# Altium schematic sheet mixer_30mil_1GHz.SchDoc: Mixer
size A4; Author: Almela; Revision: 1.2; SheetNumber: 2; SheetTotal: 7
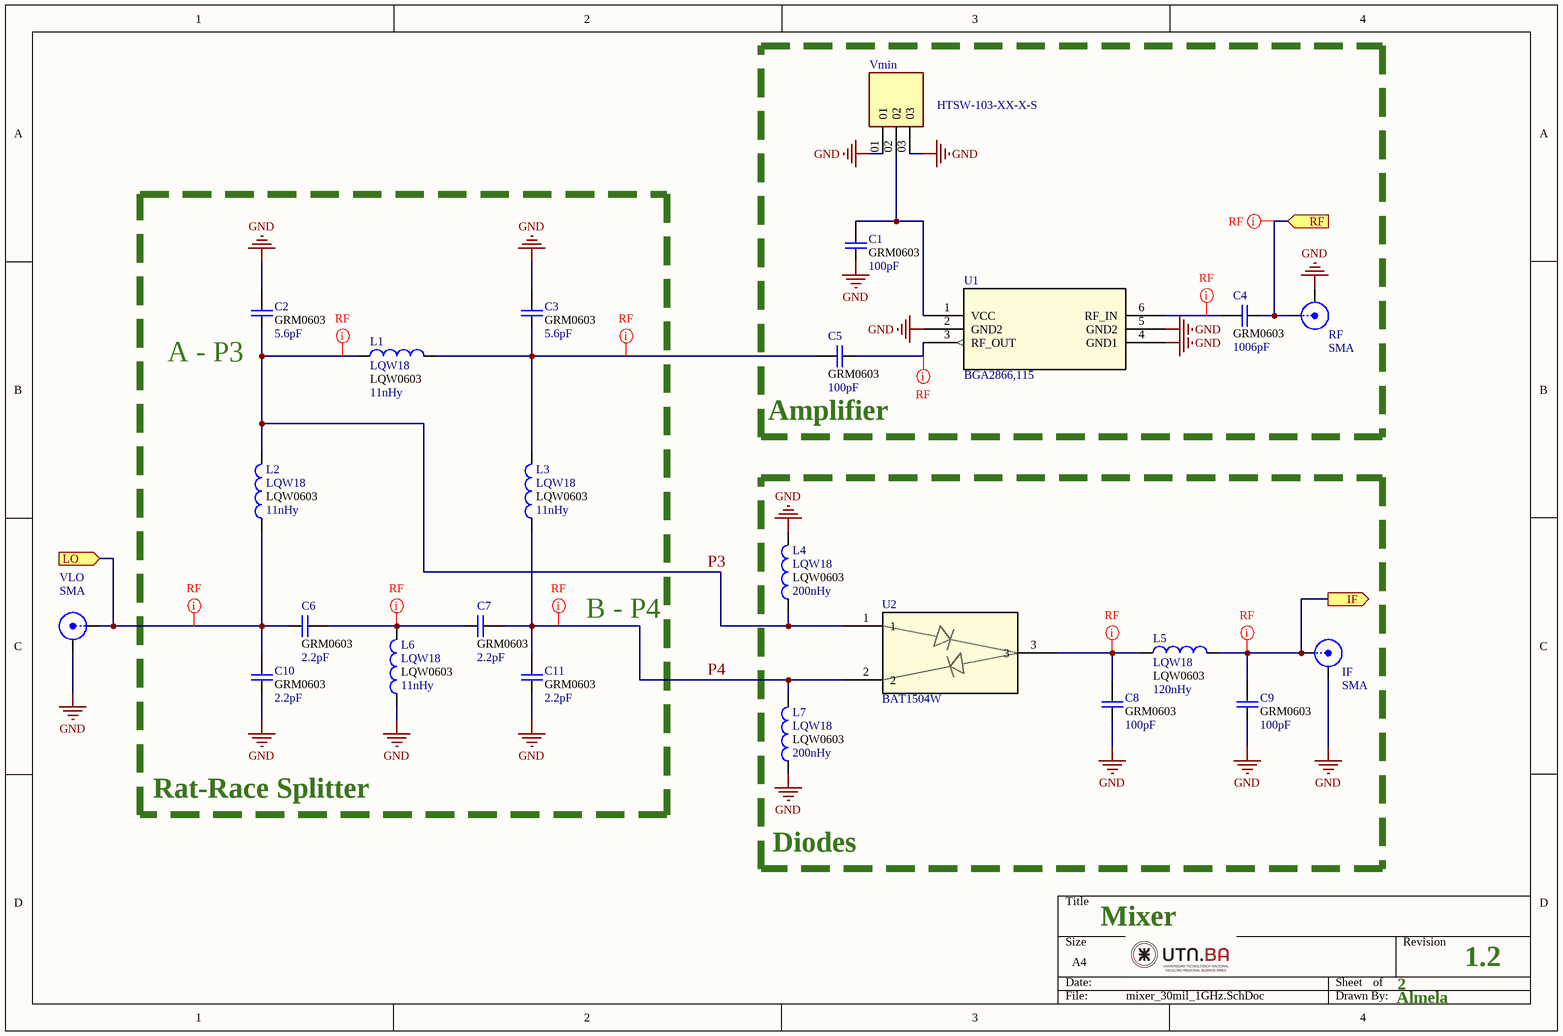
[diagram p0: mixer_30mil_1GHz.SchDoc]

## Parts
C1  value 100pF  footprint: GRM0603  [CAPC1608X90N]  (hidden comment: Cap 0603)
C2  value 5.6pF  footprint: GRM0603  [CAPC1608X90N]  (hidden comment: Cap 0603)
C3  value 5.6pF  footprint: GRM0603  [CAPC1608X90N]  (hidden comment: Cap 0603)
C4  value 1006pF  footprint: GRM0603  [CAPC1608X90N]  (hidden comment: Cap 0603)
C5  value 100pF  footprint: GRM0603  [CAPC1608X90N]  (hidden comment: Cap 0603)
C6  value 2.2pF  footprint: GRM0603  [CAPC1608X90N]  (hidden comment: Cap 0603)
C7  value 2.2pF  footprint: GRM0603  [CAPC1608X90N]  (hidden comment: Cap 0603)
C8  value 100pF  footprint: GRM0603  [CAPC1608X90N]  (hidden comment: Cap 0603)
C9  value 100pF  footprint: GRM0603  [CAPC1608X90N]  (hidden comment: Cap 0603)
C10  value 2.2pF  footprint: GRM0603  [CAPC1608X90N]  (hidden comment: Cap 0603)
C11  value 2.2pF  footprint: GRM0603  [CAPC1608X90N]  (hidden comment: Cap 0603)
IF  SMA  [SMA-142-0701-851]
L1  LQW18  value 11nHy  Parameter 1: LQW0603  [INDC1608X100N]
L2  LQW18  value 11nHy  Parameter 1: LQW0603  [INDC1608X100N]
L3  LQW18  value 11nHy  Parameter 1: LQW0603  [INDC1608X100N]
L4  LQW18  value 200nHy  Parameter 1: LQW0603  [INDC1608X100N]
L5  LQW18  value 120nHy  Parameter 1: LQW0603  [INDC1608X100N]
L6  LQW18  value 11nHy  Parameter 1: LQW0603  [INDC1608X100N]
L7  LQW18  value 200nHy  Parameter 1: LQW0603  [INDC1608X100N]
RF  SMA  [SMA-142-0701-851]
U1  BGA2866,115  [SOT363_NXP]
U2  BAT1504W  [SOT_327XTSA1_INF]
VLO  SMA  [SMA-142-0701-851]
Vmin  HTSW-103-XX-X-S  [SAMTEC_HTSW-103-XX-X-S]

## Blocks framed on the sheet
Amplifier: C1 C4 C5 RF U1 Vmin
Diodes: C8 C9 IF L4 L5 L7 U2

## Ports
IF (out), LO (in), RF (in)

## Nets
GND: C1.1 C2.2 C3.2 C8.1 C9.1 C10.1 C11.1 IF.2(Y) L4.2 L6.1 L7.1 RF.2(Y) U1.2(GND2) U1.4(GND1) U1.5(GND2) VLO.2(Y) Vmin.01 Vmin.03
IF: C9.2 IF.1(X) L5.2 ; port IF
LO: C6.1 C10.2 L2.1 VLO.1(X) ; port LO
P3: C2.1 L1.1 L2.2 L4.1 U2.1
P4: C7.2 C11.2 L3.1 L7.2 U2.2
RF: C4.1 RF.1(X) ; port RF
NetC1_2: C1.2 U1.1(VCC) Vmin.02
NetC3_1: C3.1 C5.2 L1.2 L3.2
NetC4_2: C4.2 U1.6(RF_IN)
NetC5_1: C5.1 U1.3(RF_OUT)
NetC6_2: C6.2 C7.1 L6.2
NetC8_2: C8.2 L5.1 U2.3

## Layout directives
net class RF50R: IF, LO, NetC3_1, NetC4_2, NetC5_1, NetC6_2, NetC8_2, P3, P4, RF

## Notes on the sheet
- (near C2) A - P3
- B - P4
- Rat-Race Splitter

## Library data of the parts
C1-C11 = Cap: Capacitor GRM18 0603
IF RF VLO = SMB: SMB Straight Connector
L1-L7 = LQW18: Ind RF Chip Wirewound 18nH 5% 100MHz 40Q-Factor 550mA 0603 Paper T/R; MP: LQW18AN18NJ00D
U1 = BGA2866,115: No Description Available; Mfr_Name: NXP
U2 = BAT1504W: Diodo; Mfr_Name: Infineon
Vmin = HTSW-103-XX-X-S: Conn Unshrouded Header HDR 3 POS 2.54mm Solder ST Top Entry Thru-Hole Bag; MP: HTSW-103-08-S-S; MF: Samtec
